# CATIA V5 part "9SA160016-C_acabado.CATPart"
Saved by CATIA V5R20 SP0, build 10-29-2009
Part number: 9SA160016-C_acabado
Revision: ANY
Definition: UNKNOWN
Nomenclature: 9SA160016-C_acabado
Source: Unknown
Bounding box of the stored display mesh (mm): x -8 to 8, y 0 to 16, z -8 to 8
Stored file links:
  C:\Users\Utente\Desktop\IO LAVORO\3D X SITO CF\CUMSA\3D files SA\SA 160016\9SA160016-C_acabado.CATPart
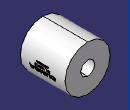
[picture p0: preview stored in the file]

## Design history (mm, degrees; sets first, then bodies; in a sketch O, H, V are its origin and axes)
Body1 "Envolver1" (main body)
  Solid1: solid without history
